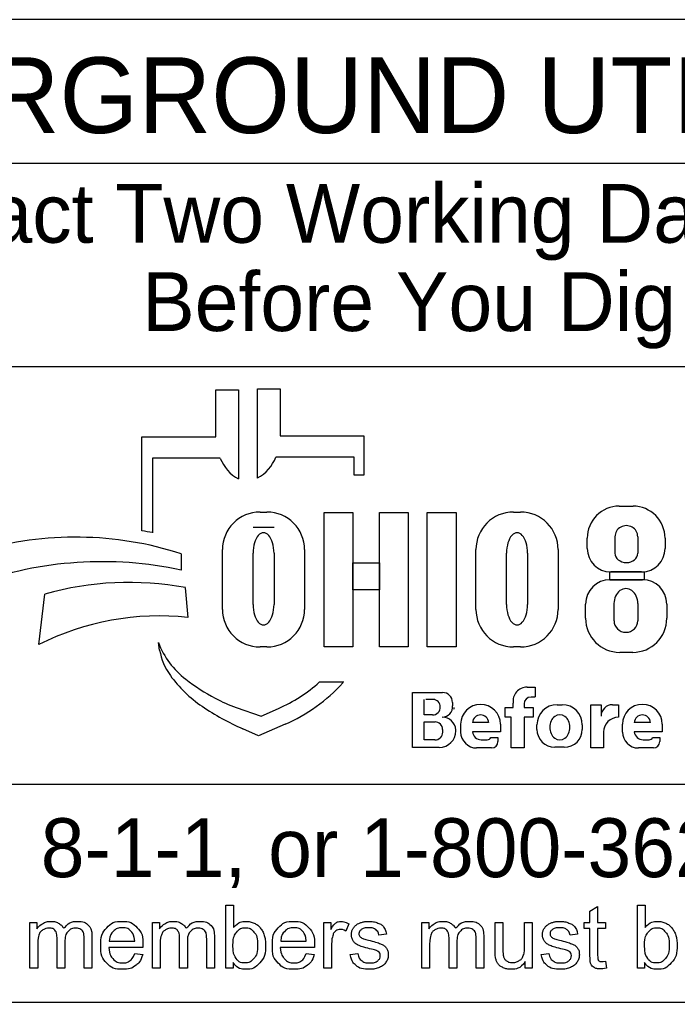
# Model space of a CAD drawing. Extents: x 0 to 42, y 0 to 22.
# Drawn here: x 3.267 to 4.831, y 2.143 to 4.48 of the extents above; entities that cross this region are included whole.
import ezdxf

# ---------------------------------------------------------------- set-up
doc = ezdxf.new("R2010")
doc.units = 0
doc.layers.add('GM_X_Adjacent_County', color=7, linetype='Continuous')
doc.layers.add('GM_X_Township', color=7, linetype='Continuous')

msp = doc.modelspace()

# ---------------------------------------------------------------- linework, layer by layer
at = {"layer": 'GM_X_Adjacent_County'}
for p, q in [((3.7335, 3.4883), (3.7335, 3.5998)), ((3.7335, 3.5998), (3.7872, 3.5998)), ((3.7872, 3.5998), (3.7872, 3.3877)), ((3.8329, 3.39), (3.8329, 3.6021)), ((3.8329, 3.6021), (3.8865, 3.6021)), ((3.8865, 3.6021), (3.8865, 3.4906)), ((3.5576, 3.2644), (3.5576, 3.4883)), ((3.5576, 3.4883), (3.7335, 3.4883)), ((3.8865, 3.4906), (4.0857, 3.4906)), ((4.0857, 3.4906), (4.0857, 3.3968)), ((3.5828, 3.4369), (3.5828, 3.26)), ((3.7439, 3.4369), (3.5828, 3.4369)), ((4.0625, 3.4392), (3.8761, 3.4392)), ((4.0625, 3.3968), (4.0625, 3.4392)), ((4.0857, 3.3968), (4.0625, 3.3968)), ((4.6931, 3.3231), (4.7258, 3.3231)), ((3.8385, 3.3091), (3.8551, 3.3091)), ((4.4416, 3.3091), (4.4581, 3.3091)), ((3.8718, 3.2721), (3.822, 3.2721)), ((4.683, 3.2111), (4.683, 3.2504)), ((4.7371, 3.2504), (4.7371, 3.2111)), ((4.6168, 3.2225), (4.6168, 3.2468)), ((4.8022, 3.2468), (4.8022, 3.2225)), ((3.6509, 3.2097), (3.6509, 3.1709)), ((3.7491, 3.0776), (3.7491, 3.2196)), ((3.822, 3.089), (3.822, 3.2114)), ((3.8718, 3.2114), (3.8718, 3.089)), ((3.9445, 3.2196), (3.9445, 3.0776)), ((4.3521, 3.0776), (4.3521, 3.2196)), ((4.425, 3.089), (4.425, 3.2114)), ((4.4748, 3.2114), (4.4748, 3.089)), ((4.5476, 3.2196), (4.5476, 3.0776)), ((4.7462, 3.1665), (4.6728, 3.1665)), ((4.671, 3.1482), (4.7483, 3.1482)), ((3.312, 2.9936), (3.3267, 3.1137)), ((3.6608, 3.1291), (3.6671, 3.0582)), ((4.6131, 3.0563), (4.6131, 3.0903)), ((4.6806, 3.0503), (4.6806, 3.0912)), ((4.7374, 3.0912), (4.7374, 3.0503)), ((4.8062, 3.0903), (4.8062, 3.0563)), ((3.5997, 2.9807), (3.5967, 2.9986)), ((3.8551, 2.9882), (3.8385, 2.9882)), ((4.4581, 2.9882), (4.4416, 2.9882)), ((4.7252, 2.9753), (4.6941, 2.9753)), ((3.98, 2.9048), (4.0375, 2.9048)), ((4.2013, 2.749), (4.2013, 2.8798)), ((4.2013, 2.8798), (4.2725, 2.8798)), ((4.4739, 2.8926), (4.4934, 2.8926)), ((4.4934, 2.8926), (4.4934, 2.8696)), ((4.2293, 2.8263), (4.2293, 2.8632)), ((4.2545, 2.8632), (4.2332, 2.8632)), ((4.2963, 2.856), (4.2963, 2.8481)), ((4.4406, 2.8442), (4.4406, 2.8546)), ((4.4667, 2.8526), (4.4667, 2.8442)), ((4.4934, 2.8691), (4.4832, 2.8691)), ((3.7816, 2.8444), (3.841, 2.8239)), ((3.841, 2.8239), (3.8821, 2.8417)), ((4.4213, 2.8212), (4.4213, 2.8442)), ((4.4213, 2.8442), (4.4406, 2.8442)), ((4.4667, 2.8442), (4.4883, 2.8442)), ((4.4883, 2.8442), (4.4883, 2.8212)), ((4.5451, 2.8508), (4.5573, 2.8508)), ((4.6254, 2.7478), (4.6254, 2.8505)), ((4.6254, 2.8505), (4.6499, 2.8505)), ((4.6499, 2.8505), (4.6499, 2.8237)), ((4.6772, 2.8505), (4.691, 2.8505)), ((4.691, 2.8505), (4.691, 2.8209)), ((4.2487, 2.8263), (4.2293, 2.8263)), ((4.2293, 2.7669), (4.2293, 2.8097)), ((4.2293, 2.8097), (4.2548, 2.8097)), ((4.3824, 2.8082), (4.3439, 2.8082)), ((4.4362, 2.8212), (4.4213, 2.8212)), ((4.4362, 2.7478), (4.4362, 2.8212)), ((4.4883, 2.8212), (4.4667, 2.8212)), ((4.4667, 2.8212), (4.4667, 2.7478)), ((4.7674, 2.8082), (4.7288, 2.8082)), ((3.835, 2.7769), (3.7976, 2.7934)), ((3.8983, 2.8044), (3.835, 2.7769)), ((4.2729, 2.7916), (4.2729, 2.7853)), ((4.3043, 2.7887), (4.3043, 2.7884)), ((4.3159, 2.7858), (4.3159, 2.8042)), ((4.4104, 2.7866), (4.344, 2.7866)), ((4.4104, 2.8042), (4.4104, 2.7866)), ((4.4973, 2.7922), (4.4973, 2.8029)), ((4.6051, 2.8029), (4.6051, 2.7922)), ((4.6559, 2.786), (4.6559, 2.7478)), ((4.7008, 2.7858), (4.7008, 2.8042)), ((4.7953, 2.7866), (4.7289, 2.7866)), ((4.7953, 2.8042), (4.7953, 2.7866)), ((4.2546, 2.7669), (4.2293, 2.7669)), ((4.3649, 2.7673), (4.379, 2.7673)), ((4.3876, 2.7729), (4.4045, 2.7729)), ((4.4045, 2.7729), (4.4045, 2.7631)), ((4.7498, 2.7673), (4.7639, 2.7673)), ((4.7725, 2.7729), (4.7894, 2.7729)), ((4.7894, 2.7729), (4.7894, 2.7631)), ((4.265, 2.749), (4.2013, 2.749)), ((4.3892, 2.7478), (4.3538, 2.7478)), ((4.4667, 2.7478), (4.4362, 2.7478)), ((4.5623, 2.7494), (4.5401, 2.7494)), ((4.6559, 2.7478), (4.6254, 2.7478)), ((4.7742, 2.7478), (4.7388, 2.7478))]:
    msp.add_line(p, q, dxfattribs=at)
for points in [[(3.991, 3.3081), (4.0589, 3.3081), (4.0589, 2.9881), (3.991, 2.9881)], [(4.1231, 3.3081), (4.1911, 3.3081), (4.1911, 2.9881), (4.1231, 2.9881)], [(4.2364, 3.3081), (4.3052, 3.3081), (4.3052, 2.9881), (4.2364, 2.9881)], [(4.0589, 3.1882), (4.1231, 3.1882), (4.1231, 3.1242), (4.0589, 3.1242)], [(4.6706, 3.1665), (4.7523, 3.1665), (4.7523, 3.1481), (4.6706, 3.1481)]]:
    msp.add_lwpolyline(points, close=True, dxfattribs=at)
for points in [[(3.7743, 2.2239), (3.7573, 2.2239), (3.7573, 2.3741), (3.7757, 2.3741), (3.7757, 2.3206)], [(4.6233, 2.2558), (4.6233, 2.3185), (4.6097, 2.3185), (4.6097, 2.3328), (4.6233, 2.3328), (4.6233, 2.3597), (4.6417, 2.3708), (4.6417, 2.3328), (4.6601, 2.3328), (4.6601, 2.3185), (4.6417, 2.3185), (4.6417, 2.2547)], [(4.7534, 2.2239), (4.7363, 2.2239), (4.7363, 2.3741), (4.7548, 2.3741), (4.7548, 2.3206)], [(3.2912, 2.2239), (3.2912, 2.3328), (3.3077, 2.3328), (3.3077, 2.3174)], [(3.5826, 2.2239), (3.5826, 2.3328), (3.5991, 2.3328), (3.5991, 2.3174)], [(3.9904, 2.2239), (3.9904, 2.3328), (4.007, 2.3328), (4.007, 2.3163)], [(4.0495, 2.3293), (4.043, 2.3122)], [(4.2236, 2.2239), (4.2236, 2.3328), (4.2401, 2.3328), (4.2401, 2.3174)], [(4.3979, 2.2654), (4.3979, 2.3328), (4.4164, 2.3328), (4.4164, 2.2724)], [(4.4676, 2.2745), (4.4676, 2.3328), (4.4861, 2.3328), (4.4861, 2.2239), (4.4696, 2.2239)], [(3.3743, 2.2871), (3.3743, 2.2239), (3.3559, 2.2239), (3.3559, 2.2946)], [(3.4388, 2.2986), (3.4388, 2.2239), (3.4203, 2.2239), (3.4203, 2.2924)], [(3.6657, 2.2871), (3.6657, 2.2239), (3.6473, 2.2239), (3.6473, 2.2946)], [(3.7301, 2.2986), (3.7301, 2.2239), (3.7117, 2.2239), (3.7117, 2.2924)], [(4.1394, 2.3046), (4.1213, 2.3022)], [(4.3067, 2.2871), (4.3067, 2.2239), (4.2883, 2.2239), (4.2883, 2.2946)], [(4.3711, 2.2986), (4.3711, 2.2239), (4.3527, 2.2239), (4.3527, 2.2924)], [(4.594, 2.3046), (4.5759, 2.3022)], [(3.3097, 2.2803), (3.3097, 2.2239), (3.2912, 2.2239)], [(3.56, 2.2736), (3.4788, 2.2736)], [(3.4799, 2.2887), (3.5406, 2.2887)], [(3.601, 2.2803), (3.601, 2.2239), (3.5826, 2.2239)], [(3.968, 2.2736), (3.8868, 2.2736)], [(3.8879, 2.2887), (3.9486, 2.2887)], [(4.0088, 2.2809), (4.0088, 2.2239), (3.9904, 2.2239)], [(4.242, 2.2803), (4.242, 2.2239), (4.2236, 2.2239)], [(3.5404, 2.2591), (3.5595, 2.2567)], [(3.9484, 2.2591), (3.9675, 2.2567)], [(4.053, 2.2564), (4.0712, 2.2593)], [(4.5076, 2.2564), (4.5258, 2.2593)], [(3.7743, 2.2375), (3.7743, 2.2239)], [(4.4696, 2.2239), (4.4696, 2.24)], [(4.6601, 2.2404), (4.6628, 2.2241)], [(4.7534, 2.2375), (4.7534, 2.2239)]]:
    msp.add_lwpolyline(points, dxfattribs=at)
for centre, radius, start, end in [((3.8353, 3.4736), 0.0985, 201.9296, 240.7469), ((3.7847, 3.476), 0.0985, 299.2531, 338.0704), ((4.6931, 3.2468), 0.0763, 90, 180), ((4.7258, 3.2468), 0.0763, 0, 90), ((3.8385, 3.2196), 0.0895, 90, 180), ((3.8551, 3.2196), 0.0895, 0, 90), ((4.4416, 3.2196), 0.0895, 90, 180), ((4.4581, 3.2196), 0.0895, 0, 90), ((3.3997, 2.4302), 0.8191, 72.1402, 106.3144), ((3.4295, 2.4554), 0.8191, 79.2074, 81.0007), ((4.6728, 3.2225), 0.056, 180, 270), ((4.7462, 3.2225), 0.056, 270, 0), ((3.4628, 2.2991), 0.8919, 77.8238, 109.8274), ((3.5267, 2.4094), 0.7322, 79.44, 105.8467), ((4.671, 3.0903), 0.0579, 90, 180), ((4.7483, 3.0903), 0.0579, 0, 90), ((3.8385, 3.0776), 0.0895, 180, 270), ((3.8551, 3.0776), 0.0895, 270, 0), ((4.4416, 3.0776), 0.0895, 180, 270), ((4.4581, 3.0776), 0.0895, 270, 0), ((3.5987, 2.4262), 0.6357, 83.8248, 116.8021), ((4.6941, 3.0563), 0.081, 180, 270), ((4.7252, 3.0563), 0.081, 270, 0), ((3.7841, 3.0707), 0.2008, 201.0457, 232.5314), ((3.741, 3.0048), 0.1433, 189.6817, 216.0884), ((3.8747, 3.1022), 0.3088, 216.0884, 235.7167), ((3.9766, 3.3219), 0.5173, 232.5314, 241.794), ((3.7387, 3.1722), 0.3602, 293.4582, 312.0712), ((3.7387, 3.1722), 0.401, 293.4582, 317.8286), ((4.2725, 2.856), 0.0238, 0, 90), ((4.4739, 2.859), 0.0335, 90, 187.5187), ((3.8914, 3.1631), 0.3371, 241.794, 250.9821), ((4.2505, 2.8463), 0.0169, 357.8325, 90), ((4.4832, 2.8526), 0.0165, 90, 180), ((4.0412, 3.3465), 0.6044, 235.7167, 246.2325), ((4.2487, 2.845), 0.0187, 270, 2.0582), ((4.2721, 2.8453), 0.0243, 270, 6.6529), ((4.2827, 2.8438), 0.0175, 347.4023, 0), ((4.3631, 2.8042), 0.0473, 0, 180), ((4.5451, 2.8029), 0.0478, 90, 180), ((4.5573, 2.8029), 0.0478, 0, 90), ((4.6768, 2.8237), 0.0269, 89.2449, 180), ((4.7481, 2.8042), 0.0473, 0, 180), ((4.2548, 2.7916), 0.0181, 0, 90), ((4.2722, 2.7889), 0.0321, 4.0748, 90), ((4.3632, 2.8072), 0.0193, 2.9632, 177.0368), ((4.6908, 2.786), 0.0349, 89.6033, 180), ((4.7481, 2.8072), 0.0193, 2.9632, 177.0368), ((4.2546, 2.7853), 0.0184, 270, 0), ((4.265, 2.7884), 0.0393, 270, 0), ((4.2714, 2.7887), 0.033, 0, 11.7502), ((4.3538, 2.7858), 0.038, 180, 270), ((4.3649, 2.7883), 0.021, 184.827, 270), ((4.5401, 2.7922), 0.0428, 180, 270), ((4.5623, 2.7922), 0.0428, 270, 0), ((4.7388, 2.7858), 0.038, 180, 270), ((4.7498, 2.7883), 0.021, 184.827, 270), ((4.379, 2.7767), 0.00938, 270, 335.9979), ((4.3892, 2.7631), 0.0152, 270, 0), ((4.7639, 2.7767), 0.00938, 270, 335.9979), ((4.7742, 2.7631), 0.0152, 270, 0)]:
    msp.add_arc(centre, radius, start, end, dxfattribs=at)
for centre, major_axis, ratio, start_param, end_param in [((4.71, 3.2504), (0.0271, 0), 0.969373, 0, 3.141593), ((3.8469, 3.2114), (0, 0.0484), 0.514403, 4.712389, 7.853982), ((4.4499, 3.2114), (0, 0.0484), 0.514403, 4.712389, 7.853982), ((4.71, 3.2111), (0.0271, 0), 0.818453, 3.141593, 6.283185), ((4.709, 3.0912), (0, 0.0358), 0.794529, 4.712389, 7.853982), ((3.8469, 3.089), (0, 0.0484), 0.514403, 1.570796, 4.712389), ((4.4499, 3.089), (0, 0.0484), 0.514403, 1.570796, 4.712389), ((4.709, 3.0503), (0.0284, 0), 0.959837, 3.141593, 6.283185), ((4.5517, 2.7976), (0, 0.029), 0.832186, 4.712389, 7.853982), ((4.5517, 2.7976), (0, 0.0302), 0.797287, 1.570796, 4.712389)]:
    msp.add_ellipse(centre, major_axis=major_axis, ratio=ratio, start_param=start_param, end_param=end_param, dxfattribs=at)
for points in [[(3.3077, 2.3174), (3.3128, 2.3254), (3.3214, 2.3303), (3.3299, 2.3352), (3.3407, 2.3352), (3.3528, 2.3352), (3.3606, 2.3301), (3.3683, 2.3251), (3.3715, 2.3161), (3.3844, 2.3352), (3.4051, 2.3352), (3.4213, 2.3352), (3.43, 2.3262), (3.4388, 2.3172), (3.4388, 2.2986)], [(3.3559, 2.2946), (3.3559, 2.3069), (3.3514, 2.313), (3.3469, 2.3191), (3.3366, 2.3191), (3.3288, 2.3191), (3.3222, 2.315), (3.3156, 2.311), (3.3126, 2.3031), (3.3097, 2.2952), (3.3097, 2.2803)], [(3.4203, 2.2924), (3.4203, 2.3035), (3.4185, 2.3083), (3.4168, 2.3132), (3.412, 2.3162), (3.4073, 2.3191), (3.401, 2.3191), (3.3895, 2.3191), (3.3819, 2.3115), (3.3743, 2.3039), (3.3743, 2.2871)], [(3.5595, 2.2567), (3.555, 2.24), (3.5428, 2.2307), (3.5306, 2.2215), (3.5117, 2.2215), (3.4878, 2.2215), (3.4738, 2.2362), (3.4598, 2.2509), (3.4598, 2.2774), (3.4598, 2.3049), (3.474, 2.32), (3.4881, 2.3352), (3.5106, 2.3352), (3.5324, 2.3352), (3.5463, 2.3203), (3.5601, 2.3055), (3.5601, 2.2785), (3.5601, 2.2769), (3.56, 2.2736)], [(3.5406, 2.2887), (3.5394, 2.3025), (3.5337, 2.3094), (3.5249, 2.3201), (3.5108, 2.3201), (3.4981, 2.3201), (3.4894, 2.3115), (3.4808, 2.303), (3.4799, 2.2887)], [(3.5991, 2.3174), (3.6042, 2.3254), (3.6127, 2.3303), (3.6212, 2.3352), (3.6321, 2.3352), (3.6442, 2.3352), (3.6519, 2.3301), (3.6597, 2.3251), (3.6628, 2.3161), (3.6758, 2.3352), (3.6965, 2.3352), (3.7127, 2.3352), (3.7214, 2.3262), (3.7301, 2.3172), (3.7301, 2.2986)], [(3.6473, 2.2946), (3.6473, 2.3069), (3.6428, 2.313), (3.6383, 2.3191), (3.628, 2.3191), (3.6202, 2.3191), (3.6136, 2.315), (3.607, 2.311), (3.604, 2.3031), (3.601, 2.2952), (3.601, 2.2803)], [(3.7117, 2.2924), (3.7117, 2.3035), (3.7099, 2.3083), (3.7081, 2.3132), (3.7034, 2.3162), (3.6987, 2.3191), (3.6923, 2.3191), (3.6809, 2.3191), (3.6733, 2.3115), (3.6657, 2.3039), (3.6657, 2.2871)], [(3.7741, 2.2792), (3.7741, 2.2596), (3.7794, 2.2509), (3.7881, 2.2366), (3.8029, 2.2366), (3.815, 2.2366), (3.8238, 2.2471), (3.8326, 2.2576), (3.8326, 2.2784), (3.8326, 2.2998), (3.8241, 2.3099), (3.8157, 2.3201), (3.8038, 2.3201), (3.7917, 2.3201), (3.7829, 2.3096), (3.7741, 2.299), (3.7741, 2.2792)], [(3.7757, 2.3206), (3.7874, 2.3352), (3.8055, 2.3352), (3.8155, 2.3352), (3.8245, 2.3311), (3.8335, 2.3271), (3.8392, 2.3198), (3.845, 2.3124), (3.8483, 2.3021), (3.8516, 2.2918), (3.8516, 2.28), (3.8516, 2.252), (3.8378, 2.2368), (3.8239, 2.2215), (3.8046, 2.2215), (3.7853, 2.2215), (3.7743, 2.2375)], [(3.9675, 2.2567), (3.963, 2.24), (3.9508, 2.2307), (3.9386, 2.2215), (3.9196, 2.2215), (3.8958, 2.2215), (3.8818, 2.2362), (3.8678, 2.2509), (3.8678, 2.2774), (3.8678, 2.3049), (3.882, 2.32), (3.8961, 2.3352), (3.9186, 2.3352), (3.9404, 2.3352), (3.9543, 2.3203), (3.9681, 2.3055), (3.9681, 2.2785), (3.9681, 2.2769), (3.968, 2.2736)], [(3.9486, 2.2887), (3.9474, 2.3025), (3.9417, 2.3094), (3.9328, 2.3201), (3.9188, 2.3201), (3.9061, 2.3201), (3.8974, 2.3115), (3.8888, 2.303), (3.8879, 2.2887)], [(4.007, 2.3163), (4.0133, 2.3278), (4.0187, 2.3315), (4.0241, 2.3352), (4.0305, 2.3352), (4.0398, 2.3352), (4.0495, 2.3293)], [(4.043, 2.3122), (4.0363, 2.3162), (4.0295, 2.3162), (4.0235, 2.3162), (4.0187, 2.3125), (4.0139, 2.3089), (4.0119, 2.3024), (4.0088, 2.2926), (4.0088, 2.2809)], [(4.1213, 2.3022), (4.1201, 2.3106), (4.1142, 2.3153), (4.1083, 2.3201), (4.0975, 2.3201), (4.0848, 2.3201), (4.0794, 2.3159), (4.0739, 2.3116), (4.0739, 2.306), (4.0739, 2.3024), (4.0762, 2.2995), (4.0785, 2.2966), (4.0833, 2.2946), (4.086, 2.2936), (4.0996, 2.2899), (4.1192, 2.2847), (4.1269, 2.2813), (4.1347, 2.278), (4.1391, 2.2717), (4.1435, 2.2653), (4.1435, 2.2559), (4.1435, 2.2467), (4.1381, 2.2386), (4.1327, 2.2304), (4.1226, 2.226), (4.1124, 2.2215), (4.0996, 2.2215), (4.0784, 2.2215), (4.0672, 2.2303), (4.0561, 2.2391), (4.053, 2.2564)], [(4.0712, 2.2593), (4.0727, 2.2483), (4.0798, 2.2425), (4.0868, 2.2366), (4.0995, 2.2366), (4.1122, 2.2366), (4.1184, 2.2418), (4.1245, 2.247), (4.1245, 2.254), (4.1245, 2.2602), (4.1191, 2.2638), (4.1153, 2.2663), (4.1002, 2.2701), (4.0799, 2.2752), (4.072, 2.2789), (4.0642, 2.2827), (4.0601, 2.2893), (4.0561, 2.2959), (4.0561, 2.3038), (4.0561, 2.3111), (4.0594, 2.3173), (4.0628, 2.3235), (4.0685, 2.3276), (4.0728, 2.3308), (4.0803, 2.333), (4.0877, 2.3352), (4.0962, 2.3352), (4.109, 2.3352), (4.1187, 2.3315), (4.1284, 2.3278), (4.133, 2.3215), (4.1377, 2.3152), (4.1394, 2.3046)], [(4.2401, 2.3174), (4.2452, 2.3254), (4.2537, 2.3303), (4.2622, 2.3352), (4.2731, 2.3352), (4.2852, 2.3352), (4.2929, 2.3301), (4.3007, 2.3251), (4.3038, 2.3161), (4.3168, 2.3352), (4.3375, 2.3352), (4.3537, 2.3352), (4.3624, 2.3262), (4.3711, 2.3172), (4.3711, 2.2986)], [(4.2883, 2.2946), (4.2883, 2.3069), (4.2838, 2.313), (4.2793, 2.3191), (4.269, 2.3191), (4.2612, 2.3191), (4.2546, 2.315), (4.248, 2.311), (4.245, 2.3031), (4.242, 2.2952), (4.242, 2.2803)], [(4.3527, 2.2924), (4.3527, 2.3035), (4.3509, 2.3083), (4.3491, 2.3132), (4.3444, 2.3162), (4.3397, 2.3191), (4.3333, 2.3191), (4.3219, 2.3191), (4.3143, 2.3115), (4.3067, 2.3039), (4.3067, 2.2871)], [(4.5759, 2.3022), (4.5747, 2.3106), (4.5688, 2.3153), (4.5629, 2.3201), (4.5521, 2.3201), (4.5394, 2.3201), (4.5339, 2.3159), (4.5285, 2.3116), (4.5285, 2.306), (4.5285, 2.3024), (4.5308, 2.2995), (4.533, 2.2966), (4.5378, 2.2946), (4.5406, 2.2936), (4.5542, 2.2899), (4.5737, 2.2847), (4.5815, 2.2813), (4.5893, 2.278), (4.5937, 2.2717), (4.5981, 2.2653), (4.5981, 2.2559), (4.5981, 2.2467), (4.5927, 2.2386), (4.5873, 2.2304), (4.5772, 2.226), (4.567, 2.2215), (4.5542, 2.2215), (4.5329, 2.2215), (4.5218, 2.2303), (4.5107, 2.2391), (4.5076, 2.2564)], [(4.5258, 2.2593), (4.5273, 2.2483), (4.5343, 2.2425), (4.5414, 2.2366), (4.554, 2.2366), (4.5668, 2.2366), (4.5729, 2.2418), (4.5791, 2.247), (4.5791, 2.254), (4.5791, 2.2602), (4.5736, 2.2638), (4.5698, 2.2663), (4.5548, 2.2701), (4.5345, 2.2752), (4.5266, 2.2789), (4.5188, 2.2827), (4.5147, 2.2893), (4.5107, 2.2959), (4.5107, 2.3038), (4.5107, 2.3111), (4.514, 2.3173), (4.5173, 2.3235), (4.5231, 2.3276), (4.5274, 2.3308), (4.5348, 2.333), (4.5423, 2.3352), (4.5508, 2.3352), (4.5636, 2.3352), (4.5733, 2.3315), (4.583, 2.3278), (4.5876, 2.3215), (4.5922, 2.3152), (4.594, 2.3046)], [(4.7532, 2.2792), (4.7532, 2.2596), (4.7585, 2.2509), (4.7672, 2.2366), (4.782, 2.2366), (4.7941, 2.2366), (4.8029, 2.2471), (4.8116, 2.2576), (4.8116, 2.2784), (4.8116, 2.2998), (4.8032, 2.3099), (4.7948, 2.3201), (4.7828, 2.3201), (4.7708, 2.3201), (4.762, 2.3096), (4.7532, 2.299), (4.7532, 2.2792)], [(4.7548, 2.3206), (4.7664, 2.3352), (4.7846, 2.3352), (4.7946, 2.3352), (4.8036, 2.3311), (4.8125, 2.3271), (4.8183, 2.3198), (4.8241, 2.3124), (4.8274, 2.3021), (4.8306, 2.2918), (4.8306, 2.28), (4.8306, 2.252), (4.8168, 2.2368), (4.803, 2.2215), (4.7836, 2.2215), (4.7644, 2.2215), (4.7534, 2.2375)], [(3.4788, 2.2736), (3.4799, 2.2557), (3.489, 2.2462), (3.4981, 2.2366), (3.5117, 2.2366), (3.5219, 2.2366), (3.5291, 2.242), (3.5362, 2.2473), (3.5404, 2.2591)], [(3.8868, 2.2736), (3.8879, 2.2557), (3.897, 2.2462), (3.9061, 2.2366), (3.9197, 2.2366), (3.9299, 2.2366), (3.937, 2.242), (3.9442, 2.2473), (3.9484, 2.2591)], [(4.4164, 2.2724), (4.4164, 2.258), (4.4175, 2.253), (4.4192, 2.2457), (4.4249, 2.2416), (4.4305, 2.2374), (4.4388, 2.2374), (4.4471, 2.2374), (4.4543, 2.2417), (4.4616, 2.2459), (4.4646, 2.2533), (4.4676, 2.2606), (4.4676, 2.2745)], [(4.4696, 2.24), (4.4569, 2.2215), (4.4351, 2.2215), (4.4255, 2.2215), (4.4171, 2.2252), (4.4088, 2.2289), (4.4047, 2.2345), (4.4007, 2.2401), (4.3991, 2.2482), (4.3979, 2.2536), (4.3979, 2.2654)], [(4.6628, 2.2241), (4.655, 2.2224), (4.6488, 2.2224), (4.6388, 2.2224), (4.6333, 2.2256), (4.6278, 2.2288), (4.6255, 2.234), (4.6233, 2.2392), (4.6233, 2.2558)], [(4.6417, 2.2547), (4.6417, 2.2468), (4.6427, 2.2445), (4.6436, 2.2423), (4.6458, 2.2409), (4.648, 2.2396), (4.6521, 2.2396), (4.6551, 2.2396), (4.6601, 2.2404)]]:
    msp.add_open_spline(points, degree=3, dxfattribs=at)
at = {"layer": 'GM_X_Township'}
for p, q in [((6.6275, 4.4803), (2.3775, 4.4803)), ((2.3775, 4.1387), (6.6275, 4.1387)), ((2.3775, 3.6553), (6.6275, 3.6553)), ((6.6275, 2.6607), (2.3775, 2.6607)), ((6.6275, 2.1428), (2.3775, 2.1428))]:
    msp.add_line(p, q, dxfattribs=at)

# ---------------------------------------------------------------- texts
at = {"layer": 'GM_X_Adjacent_County'}
for s, height, p in [('UNDERGROUND UTILITIES', 0.18, (2.5057, 4.2106)), ('Contact Two Working Days', 0.14, (2.7972, 3.9496)), ('Before You Dig', 0.14, (3.5583, 3.7396)), ('OHIO811, 8-1-1, or 1-800-362-2764', 0.14, (2.422, 2.4406))]:
    msp.add_text(s, height=height, dxfattribs=at).set_placement(p)

doc.saveas('drawing.dxf')
